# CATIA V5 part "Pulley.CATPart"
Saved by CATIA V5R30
Part number: Pulley
Bounding box of the stored display mesh (mm): x -40.838 to 40.838, y -33 to 33, z -40.838 to 40.838
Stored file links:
  D:\PROJECTS\CATIA V56R 2020\Resources\Parts File\c14_catia_v5_6r2020_prt\c14-catia-v5-6r2020-figr-14-26 & 27\Part & Asm\Pulley.CATPart
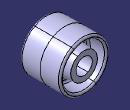
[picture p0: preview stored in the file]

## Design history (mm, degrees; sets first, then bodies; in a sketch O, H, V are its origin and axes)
Body1 (main body)
  Sketch1 on yz-plane, origin (0, 0, 0), H (0, 1, 0), V (0, 0, 1)
    line L1 (0, 13.45) -> (31.5, 13.45)
    point P1 (0, 13.45)
    point P2 (31.5, 13.45)
    line L2 (31.5, 13.45) -> (31.5, 22)
    point P3 (31.5, 22)
    line L3 (31.5, 22) -> (6, 24)
    point P4 (6, 24)
    line L4 (6, 24) -> (6, 33)
    point P5 (6, 33)
    line L5 (6, 33) -> (33, 35)
    point P6 (33, 35)
    line L6 (33, 35) -> (33, 41)
    point P7 (33, 41)
    line L7 (33, 41) -> (0, 41)
    point P8 (0, 41)
    point P9 (0, 41)
    point P10 (-33, 41)
    line L8 (-33, 41) -> (0, 41)
    point P11 (-33, 35)
    line L9 (-33, 35) -> (-33, 41)
    point P12 (-6, 33)
    line L10 (-6, 33) -> (-33, 35)
    point P13 (-6, 24)
    line L11 (-6, 24) -> (-6, 33)
    point P14 (-31.5, 22)
    line L12 (-31.5, 22) -> (-6, 24)
    point P15 (-31.5, 13.45)
    line L13 (-31.5, 13.45) -> (-31.5, 22)
    point P16 (0, 13.45)
    line L14 (0, 13.45) -> (-31.5, 13.45)
    length L1 = 31.5
    distance L1 H = 13.45
    distance P4 H = 24
    distance P3 H = 22
    distance L4 V = 6
    distance P5 H = 33
    distance P6 H = 35
    distance V L6 = 33
    distance L7 H = 41
    coincidence: P1 V, P8 V, P1 P16, P8 P9
    horizontal: L1 H, L7 H
    vertical: L2 V, L4 V, L6 V
    symmetry: P8 P9 V, P7 P10 V, L7 L8 V, P6 P11 V, L6 L9 V, P5 P12 V, L5 L10 V, P4 P13 V, L4 L11 V, P3 P14 V, L3 L12 V, P2 P15 V, L2 L13 V, P1 P16 V, L1 L14 V
  Shaft1: profile Sketch1, axis Sketch1.H, angle 360
  Fillet1: radius 3, on 4 faces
